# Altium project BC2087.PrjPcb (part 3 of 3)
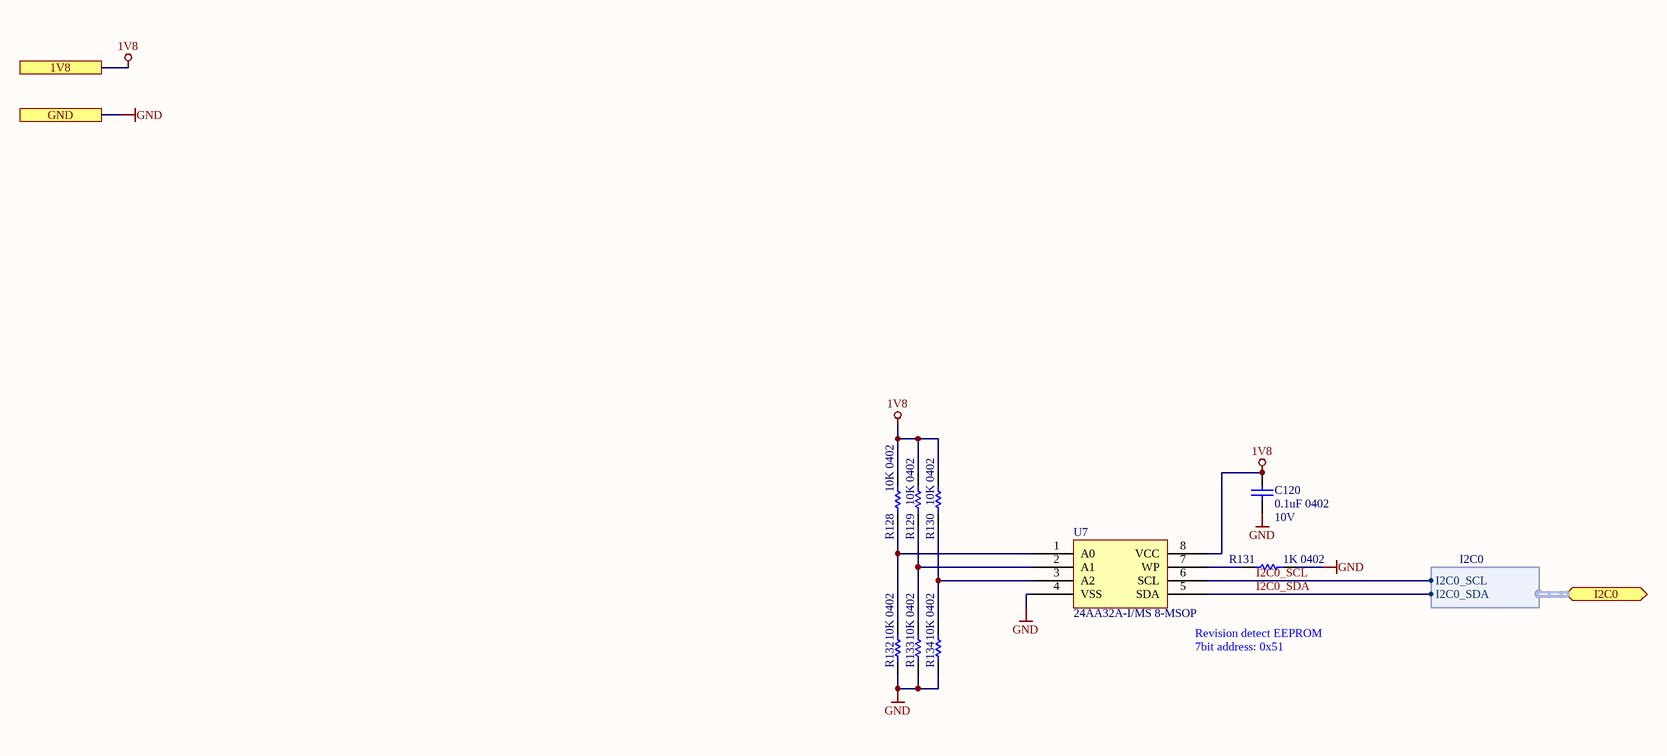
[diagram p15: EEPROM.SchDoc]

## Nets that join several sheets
1V2: POWER_GEN (5 pins), MID_AR0234 (FB12.1), RIGHT_AR0234 (FB9.1), LEFT_AR0234 (FB6.1)
1V8: CONNECTOR_B (9 pins), ETH_PCIE_PHY (C52.2 R50.2 U6.3), BOOT_JTAG_AUX (J4.7 P1.1), POWER_GEN (C60.2 TP16.1 U10.5), MID_AR0234 (FB11.1), RIGHT_AR0234 (FB8.1), LEFT_AR0234 (FB5.1), IMU (9 pins), EEPROM (5 pins)
2V8: POWER_GEN (C66.2 TP23.1 U14.1), MID_AR0234 (FB10.1), RIGHT_AR0234 (FB7.1), LEFT_AR0234 (FB4.1)
3V3: ETH_PCIE_PHY (15 pins), RJ45 (D16.2 J1.15 J1.17), USB (7 pins), BOOT_JTAG_AUX (C55.2 J4.9 J7.4), POWER_GEN (8 pins), IMU (5 pins)
5V_PoE: PoE_Si3404 (7 pins), POWER_GEN (5 pins)
GND: TopLevel (5 pins), CONNECTOR_B (36 pins), CONNECTOR_A (33 pins), ETH_PCIE_PHY (26 pins), RJ45 (7 pins), USB (28 pins), BOOT_JTAG_AUX (18 pins), PoE_Si3404 (9 pins), POWER_GEN (22 pins), MID_AR0234 (19 pins), RIGHT_AR0234 (19 pins), LEFT_AR0234 (19 pins), IMU (14 pins), EEPROM (6 pins)
VBUS: CONNECTOR_B (J3.80), USB (11 pins), POWER_GEN (R69.2 TP20.1 U8.1)
VDD_5V: CONNECTOR_B (8 pins), USB (C76.2 R213.2 R214.2 U62.12), BOOT_JTAG_AUX (D3.2 D7.2 D12.1 R55.2), POWER_GEN (14 pins)
VNEG_IN: RJ45 (D1.4 D8.4), PoE_Si3404 (C33.1 FB3.1)
2485_PGOOD: CONNECTOR_A (J2.37), BOOT_JTAG_AUX (J5.5 Q2.1)
2485_WAKEUP: CONNECTOR_A (J2.41 R62.1), BOOT_JTAG_AUX (J5.7)
BMI270_INT_1V8: CONNECTOR_B (J3.66), IMU (U9.4)
BMI270_WAKE_1V8: CONNECTOR_B (J3.72), IMU (U9.9)
BNO08x_BOOTN_1V8: CONNECTOR_B (J3.54), IMU (R32.2)
BNO08x_RSTn_1V8: CONNECTOR_B (J3.44), IMU (TP34.1 U11.11)
BNO085_INT_1V8: CONNECTOR_B (J3.62), IMU (TP35.1 U11.14)
BNO085_WAKE_1V8: CONNECTOR_B (J3.60), IMU (U11.6)
BOOT0/LED_B: CONNECTOR_B (J3.26 R16.1 R23.2), BOOT_JTAG_AUX (Q6.1)
BOOT2/LED_R: CONNECTOR_B (J3.22 R7.1 R21.2 R45.2), BOOT_JTAG_AUX (Q3.1)
BOOT7/LED_G: CONNECTOR_B (J3.28 R68.1 R80.2 R81.2), BOOT_JTAG_AUX (Q5.1)
BRIDGE_REFCLK_N: CONNECTOR_B (J3.81), ETH_PCIE_PHY (R25.2)
BRIDGE_REFCLK_P: CONNECTOR_B (J3.83), ETH_PCIE_PHY (R6.2)
CAM_A_CLK_OUT: CONNECTOR_A (J2.28), MID_AR0234 (J6.3)
CAM_A_PWDN_N: CONNECTOR_A (J2.34), MID_AR0234 (J6.9 R70.2)
CAM_B_CLK_OUT: CONNECTOR_A (J2.73), RIGHT_AR0234 (J9.3), LEFT_AR0234 (J10.3)
CAM_B_PWDN_N: CONNECTOR_A (J2.67), LEFT_AR0234 (J10.9 R37.1)
CAM_R_PWM: CONNECTOR_B (J3.74), RIGHT_AR0234 (J9.9 R43.2)
COM_AUX_IO2: CONNECTOR_B (R83.1), CONNECTOR_A (R82.1), BOOT_JTAG_AUX (J5.8), LEFT_AR0234 (R39.2)
FSIN2: RIGHT_AR0234 (J9.8), LEFT_AR0234 (R77.2)
FSIN3: MID_AR0234 (J6.8), LEFT_AR0234 (R38.2)
GPIO7/sd_hst_cd: CONNECTOR_A (J2.59), BOOT_JTAG_AUX (R66.2)
I2C0_SCL: CONNECTOR_B (J3.34), BOOT_JTAG_AUX (TP1.1), EEPROM (U7.6)
I2C0_SDA: CONNECTOR_B (J3.36), BOOT_JTAG_AUX (TP2.1), EEPROM (U7.5)
I2C1_SCL: CONNECTOR_A (J2.35), MID_AR0234 (J6.7)
I2C1_SDA: CONNECTOR_A (J2.33), MID_AR0234 (J6.5)
I2C2_SCL: CONNECTOR_A (J2.77), LEFT_AR0234 (J10.7)
I2C2_SDA: CONNECTOR_A (J2.79), LEFT_AR0234 (J10.5)
I2C3_SCL: CONNECTOR_A (J2.78), BOOT_JTAG_AUX (J5.2), RIGHT_AR0234 (J9.7)
I2C3_SDA: CONNECTOR_A (J2.80), BOOT_JTAG_AUX (J5.4), RIGHT_AR0234 (J9.5)
I2C4_SCL_1V8: CONNECTOR_B (J3.59), BOOT_JTAG_AUX (P1.3)
I2C4_SDA_1V8: CONNECTOR_B (J3.57), BOOT_JTAG_AUX (P1.2)
LED0_10_GRN: ETH_PCIE_PHY (U4.27), RJ45 (R57.1)
LED1_100_OR: ETH_PCIE_PHY (U4.26), RJ45 (R58.1)
LED2_1000_GRN: ETH_PCIE_PHY (U4.25), RJ45 (R59.1)
MD1_N: ETH_PCIE_PHY (U4.2), RJ45 (D17.2 D17.9 J1.2)
MD1_P: ETH_PCIE_PHY (U4.1), RJ45 (D17.1 D17.10 J1.1)
MD2_N: ETH_PCIE_PHY (U4.5), RJ45 (D17.5 D17.6 J1.6)
MD2_P: ETH_PCIE_PHY (U4.4), RJ45 (D17.4 D17.7 J1.3)
MD3_N: ETH_PCIE_PHY (U4.7), RJ45 (D18.2 D18.9 J1.8)
MD3_P: ETH_PCIE_PHY (U4.6), RJ45 (D18.1 D18.10 J1.7)
MD4_N: ETH_PCIE_PHY (U4.10), RJ45 (D18.5 D18.6 J1.10)
MD4_P: ETH_PCIE_PHY (U4.9), RJ45 (D18.4 D18.7 J1.9)
MIPI_RX2_C_N: CONNECTOR_A (J2.95), LEFT_AR0234 (J10.20)
MIPI_RX2_C_P: CONNECTOR_A (J2.97), LEFT_AR0234 (J10.19)
MIPI_RX2_D0_N: CONNECTOR_A (J2.89), LEFT_AR0234 (J10.26)
MIPI_RX2_D0_P: CONNECTOR_A (J2.91), LEFT_AR0234 (J10.25)
MIPI_RX2_D1_N: CONNECTOR_A (J2.83), LEFT_AR0234 (J10.22)
MIPI_RX2_D1_P: CONNECTOR_A (J2.85), LEFT_AR0234 (J10.23)
MIPI_RX3_C_N: CONNECTOR_A (J2.96), RIGHT_AR0234 (J9.20)
MIPI_RX3_C_P: CONNECTOR_A (J2.98), RIGHT_AR0234 (J9.19)
MIPI_RX3_D0_N: CONNECTOR_A (J2.90), RIGHT_AR0234 (J9.26)
MIPI_RX3_D0_P: CONNECTOR_A (J2.92), RIGHT_AR0234 (J9.25)
MIPI_RX3_D1_N: CONNECTOR_A (J2.84), RIGHT_AR0234 (J9.22)
MIPI_RX3_D1_P: CONNECTOR_A (J2.86), RIGHT_AR0234 (J9.23)
MIPI_RX4_C_N: CONNECTOR_A (J2.3), MID_AR0234 (J6.20)
MIPI_RX4_C_P: CONNECTOR_A (J2.5), MID_AR0234 (J6.19)
MIPI_RX4_D0_N: CONNECTOR_A (J2.9), MID_AR0234 (J6.26)
MIPI_RX4_D0_P: CONNECTOR_A (J2.11), MID_AR0234 (J6.25)
MIPI_RX4_D1_N: CONNECTOR_A (J2.15), MID_AR0234 (J6.22)
MIPI_RX4_D1_P: CONNECTOR_A (J2.17), MID_AR0234 (J6.23)
MIPI_RX5_D0_N: CONNECTOR_A (J2.21), MID_AR0234 (J6.16)
MIPI_RX5_D0_P: CONNECTOR_A (J2.23), MID_AR0234 (J6.17)
MIPI_RX5_D1_N: CONNECTOR_A (J2.27), MID_AR0234 (J6.14)
MIPI_RX5_D1_P: CONNECTOR_A (J2.29), MID_AR0234 (J6.13)
MODULE_nRST: CONNECTOR_A (B1.2 J2.39), BOOT_JTAG_AUX (J5.1 Q4.1)
PCIe_CLKREQ_N_1V8: CONNECTOR_B (J3.65), ETH_PCIE_PHY (U6.4)
PCIe_ISOLATE_N_1V8: CONNECTOR_B (R27.2), ETH_PCIE_PHY (U6.5)
PCIe_PERST_1V8: CONNECTOR_B (J3.68), ETH_PCIE_PHY (Q1.1)
sd_hst0_clk: CONNECTOR_A (J2.61), BOOT_JTAG_AUX (J7.5)
sd_hst0_cmd: CONNECTOR_A (J2.63), BOOT_JTAG_AUX (J7.3)
sd_hst0_dat_0: CONNECTOR_A (J2.40), BOOT_JTAG_AUX (J7.7)
sd_hst0_dat_1: CONNECTOR_A (J2.38), BOOT_JTAG_AUX (J7.8)
sd_hst0_dat_2: CONNECTOR_A (J2.36), BOOT_JTAG_AUX (J7.1)
sd_hst0_dat_3: CONNECTOR_A (J2.32), BOOT_JTAG_AUX (J7.2)
SDS_RXD_N: CONNECTOR_B (J3.77), ETH_PCIE_PHY (C51.1)
SDS_RXD_P: CONNECTOR_B (J3.75), ETH_PCIE_PHY (C35.1)
SDS_TXD_N: CONNECTOR_B (J3.71), ETH_PCIE_PHY (U4.14)
SDS_TXD_P: CONNECTOR_B (J3.69), ETH_PCIE_PHY (U4.13)
SPI_BMI270_CS_1V8: CONNECTOR_A (J2.60 TP30.1), IMU (U9.12)
SPI_BNO085_CS_1V8: CONNECTOR_A (J2.70), IMU (U11.18)
SPI_MISO_1V8: CONNECTOR_A (J2.64 TP28.1), IMU (U9.1 U11.20)
SPI_MOSI_1V8: CONNECTOR_A (J2.62 TP29.1), IMU (U9.14 U11.17)
SPI_SCK_1V8: CONNECTOR_A (J2.74 TP27.1), IMU (U9.13 U11.19)
STRBL: BOOT_JTAG_AUX (J5.6), LEFT_AR0234 (J10.10 TP15.1)
SYS_RST: CONNECTOR_B (J3.89), BOOT_JTAG_AUX (J4.6)
TCK: CONNECTOR_B (J3.97), BOOT_JTAG_AUX (J4.2)
TDI: CONNECTOR_B (J3.95), BOOT_JTAG_AUX (J4.3)
TDO: CONNECTOR_B (J3.91), BOOT_JTAG_AUX (J4.5)
TMS: CONNECTOR_B (J3.99), BOOT_JTAG_AUX (J4.1)
TRST: CONNECTOR_B (J3.93), BOOT_JTAG_AUX (J4.4)
USB_D_N: CONNECTOR_B (J3.90), USB (D11.2 D11.9 J8.A7 J8.B7)
USB_D_P: CONNECTOR_B (J3.92), USB (D11.1 D11.10 J8.A6 J8.B6)
USB_RX_N: CONNECTOR_B (J3.96), USB (U61.4)
USB_RX_P: CONNECTOR_B (J3.98), USB (U61.3)
USB_TX_N: CONNECTOR_B (J3.84), USB (U61.8)
USB_TX_P: CONNECTOR_B (J3.86), USB (U61.7)
VPOS_IN: RJ45 (D1.1 D8.1), PoE_Si3404 (C33.2 FB2.1)

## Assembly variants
Production_MX: not fitted B1 J4 R1 R2 R7 R22 R23 R35 R40 R47 R66 R67 R68 R80 R82 R129 R130 R132 SW2 SW3
Production_KeemBay: not fitted B1 J4 R1 R20 R21 R22 R23 R35 R40 R44 R45 R47 R66 R67 R68 R83 R129 R130 R132 SW2 SW2 SW3 U9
